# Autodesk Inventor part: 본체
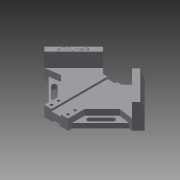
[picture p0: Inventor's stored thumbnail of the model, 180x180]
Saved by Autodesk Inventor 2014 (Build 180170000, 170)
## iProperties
Created: 2020-05
Part Number: 본체
Material: Generic
Document SubType Name: Modeling
Designer: kh
Density: 1 g/cm^3
Appearance: Default
Author: kh
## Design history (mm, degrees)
sketch "스케치1"
  geometry: L1 (0, 0)-(0, 178.142); L2 (0, 169.706)-(84.853, 84.853); L3 (84.853, 84.853)-(0, 0); L4 (0, 169.706)-(-84.853, 84.853); L5 (-84.853, 84.853)-(0, 0)
  constraints: 10 end point, 1 perpendicular, 1 point on line, 1 symmetric about line, 1 vertical
  dimensions: "d0" = 120 distance of L2.start L2.end; "d1" = 120 distance of L2.end L1.start
extrude "돌출1" new body sketch "스케치1" distance "d2" = 42; taper "d3" = 0 deg
sketch "스케치2"
  geometry: L1 (0, 0)-(84.853, 84.853) reference; L2 (84.853, 84.853)-(0, 169.706) reference; L3 (0, 169.706)-(-84.853, 84.853) reference; L4 (-84.853, 84.853)-(0, 0) reference; L5 (0, 169.706)-(-35.355, 134.35); L6 (-35.355, 134.35)-(0, 98.995); L7 (35.355, 134.35)-(0, 98.995); L8 (35.355, 134.35)-(0, 169.706); L9 (0, 169.706)-(0, 0); L10 (0, 0)-(0, 20); L11 (-20, 20)-(20, 20); L12 (0, 20)-(0, 115); L13 (-16.005, 115)-(16.005, 115); L14 (-20, 20)-(0, 0); L15 (0, 0)-(20, 20); 1 further point
  constraints: 22 end point, 8 point on line, 4 perpendicular, 2 collinear, 2 midpoint, 1 parallel, 1 vertical
  dimensions: "d4" = 50 distance of L5.end L6.end; "d5" = 50 distance of L7.start L6.end; "d6" = 20 distance of L1.start L10.end; "d7" = 95 distance of L10.end L12.end
  node "투영된 루프1"
extrude "돌출2" cut sketch "스케치2" stored distance "d8" = 42; taper "d9" = 0 deg
extrude "돌출3" cut sketch "스케치2" stored distance "d10" = 42; taper "d11" = 0 deg
sketch "스케치3"
  geometry: L1 (-20, 20)-(20, 20) reference; L2 (20, 20)-(84.853, 84.853) reference; L3 (84.853, 84.853)-(35.355, 134.35) reference; L4 (35.355, 134.35)-(16.005, 115) reference; L5 (16.005, 115)-(-16.005, 115) reference; L6 (-16.005, 115)-(-35.355, 134.35) reference; L7 (-35.355, 134.35)-(-84.853, 84.853) reference; L8 (-84.853, 84.853)-(-20, 20) reference; L9 (24.749, 123.744)-(74.246, 74.246); L10 (24.749, 123.744)-(35.355, 134.35); L11 (35.355, 134.35)-(84.853, 84.853); L12 (84.853, 84.853)-(74.246, 74.246); L13 (0, 0)-(0, 115); L14 (-84.853, 84.853)-(-35.355, 134.35); L15 (-24.749, 123.744)-(-74.246, 74.246); L16 (-24.749, 123.744)-(-35.355, 134.35); L17 (-35.355, 134.35)-(-84.853, 84.853); L18 (-84.853, 84.853)-(-74.246, 74.246); L19 (-24.749, 123.744)-(-16.005, 115); L20 (16.005, 115)-(24.749, 123.744); L21 (-16.005, 115)-(16.005, 115); L22 (-74.246, 74.246)-(-20, 20); L23 (-20, 20)-(20, 20); L24 (20, 20)-(74.246, 74.246)
  constraints: 32 end point, 8 collinear, 2 point on line, 2 symmetric about line, 1 midpoint, 1 parallel, 1 perpendicular
  dimensions: "d12" = 15 distance between parallel lines of L9 L3
extrude "돌출4" cut sketch "스케치3" distance "d13" = 24; taper "d14" = 0 deg
chamfer "모따기1" distance "d15" = 5; stored, may be unused: second distance "d16" = 15, angle "d17" = 45 deg
chamfer "모따기2" distance "d18" = 5; stored, may be unused: second distance "d19" = 15, angle "d20" = 45 deg
sketch "스케치4"
  geometry: L1 (20, 20)-(-20, 20) reference; L2 (74.246, 74.246)-(20, 20) reference; L3 (24.749, 123.744)-(74.246, 74.246) reference; L4 (16.005, 115)-(24.749, 123.744) reference; L5 (-16.005, 115)-(16.005, 115) reference; L6 (-24.749, 123.744)-(-16.005, 115) reference; L7 (-74.246, 74.246)-(-24.749, 123.744) reference; L8 (-20, 20)-(-74.246, 74.246) reference; L9 (0, 0)-(0, 115); L10 (-8, 115)-(8, 115); L11 (8, 115)-(8, 20); L12 (8, 20)-(-8, 20); L13 (-8, 20)-(-8, 115); L14 (20, 20)-(20, 48.284); L15 (20, 48.284)-(49.497, 77.782); L16 (49.497, 77.782)-(74.246, 74.246); L17 (84.853, 84.853)-(35.355, 134.35) reference; L18 (29.698, 46.669)-(49.497, 66.468); L19 (26.87, 49.497)-(46.669, 69.296); L20 (52.326, 63.64)-(32.527, 43.841); L21 (20, 27.071)-(68.059, 75.13); L22 (20, 20)-(74.246, 74.246); L23 (-49.497, 77.782)-(-74.246, 74.246); L24 (-24.749, 123.744)-(-74.246, 74.246); L25 (-20, 20)-(-74.246, 74.246); L26 (-26.87, 49.497)-(-46.669, 69.296); L27 (-20, 48.284)-(-49.497, 77.782); L28 (-29.698, 46.669)-(-49.497, 66.468); L29 (-52.326, 63.64)-(-32.527, 43.841); L30 (-20, 27.071)-(-68.059, 75.13); L31 (-74.246, 74.246)-(-20, 20); L32 (-20, 20)-(-20, 48.284); A1 r 4 centre (29.698, 46.669) between (26.87, 49.497) and (32.527, 43.841); A2 r 4 centre (49.497, 66.468) between (52.326, 63.64) and (46.669, 69.296); A3 r 4 centre (-49.497, 66.468) between (-46.669, 69.296) and (-52.326, 63.64); A4 r 4 centre (-29.698, 46.669) between (-32.527, 43.841) and (-26.87, 49.497); 3 further points
  constraints: 50 end point, 13 symmetric about line, 8 point on circle, 7 point on line, 5 parallel, 4 centre point, 4 tangent, 3 perpendicular, 2 midpoint, 1 horizontal, 3 other
  dimensions: "d21" = 16 distance of L10.start L10.end; "d27" = 20 distance from line of L9 L14.start; "d28" = 30 distance from line of L15.end L17; "d29" = 28 distance of L18.start L18.end; "d30" = 4 radius of A2; "d31" = 38 distance from line of L18.end L17; "d32" = 20 distance from line of L2 L15.end; "d33" = 12 distance from line of L2 L18.end; "d34" = 5 distance between parallel lines of L21 L2
  node "투영된 루프3"
extrude "돌출5" cut sketch "스케치4" distance "d22" = 3.5; taper "d23" = 0 deg
sketch "스케치5"
  geometry: L1 (-20, 20)-(20, 20) reference; L2 (84.853, 84.853)-(20, 20) reference; L3 (35.355, 134.35)-(84.853, 84.853) reference; L4 (35.355, 134.35)-(16.005, 115) reference; L5 (16.005, 115)-(-16.005, 115) reference; L6 (-16.005, 115)-(-35.355, 134.35) reference; L7 (-84.853, 84.853)-(-35.355, 134.35) reference; L8 (-20, 20)-(-84.853, 84.853) reference; L9 (0, 115)-(0, 0); L10 (-6, 115)-(6, 115); L11 (6, 115)-(6, 20); L12 (6, 20)-(-6, 20); L13 (-6, 20)-(-6, 115)
  constraints: 10 end point, 2 parallel, 2 perpendicular, 2 point on line, 1 horizontal, 1 midpoint, 1 other
  dimensions: "d24" = 12 distance of L10.start L10.end
extrude "돌출6" cut sketch "스케치5" distance "d25" = 3; taper "d26" = 0 deg
extrude "돌출7" cut sketch "스케치4" stored distance "d35" = 3; taper "d36" = 0 deg
extrude "돌출8" cut sketch "스케치4" distance "d37" = 10; taper "d38" = 0 deg
sketch "스케치6"
  geometry: L1 (20, 20)-(20, 48.284) reference; L2 (20, 48.284)-(49.497, 77.782) reference; L3 (49.497, 77.782)-(74.246, 74.246) reference; L4 (24.749, 123.744)-(74.246, 74.246) reference; L5 (16.005, 115)-(24.749, 123.744) reference; L6 (8, 115)-(16.005, 115) reference; L7 (8, 115)-(8, 20) reference; L8 (20, 20)-(8, 20) reference; 3 further points
  constraints: 1 vertical alignment
  dimensions: "d39" = 12 distance of point (14, 26) point (14, 38); "d40" = 6 distance from line of L8 point (14, 26); "d41" = 14 horizontal distance of point (0, 0) point (14, 26)
hole "구멍1" sketch "스케치6" at (14, 38), (14, 26) diameter "d42" = 4.5; stored, may be unused: countersink angle "d46" = 90 deg, drill point angle "d48" = 118 deg; dims "d43" = 6, "d44" = 4, "d45" = 2, "d47" = 8
sketch "스케치7"
  geometry: L1 (-74.246, 74.246)-(-68.059, 75.13) reference; L2 (-68.059, 75.13)-(-20, 27.071) reference; L3 (-20, 27.071)-(-20, 20) reference; L4 (-20, 20)-(-6, 20) reference; L5 (-6, 20)-(-6, 115) reference; L6 (-6, 115)-(-16.005, 115) reference; L7 (-16.005, 115)-(-35.355, 134.35) reference; L8 (-84.853, 84.853)-(-35.355, 134.35) reference; L9 (-74.246, 74.246)-(-84.853, 84.853) reference; L10 (-32.527, 43.841)-(-52.326, 63.64) reference; L11 (-46.669, 69.296)-(-26.87, 49.497) reference; C1 r 2.25 at (-14, 38) reference; C2 r 2.25 at (-14, 26) reference; C3 r 4 at (-14, 38); C4 r 4 at (-14, 26); A1 r 4 centre (-29.698, 46.669) between (-32.527, 43.841) and (-26.87, 49.497) reference; A2 r 4 centre (-49.497, 66.468) between (-46.669, 69.296) and (-52.326, 63.64) reference; 1 further point
  constraints: 2 centre point, 2 coincident
  dimensions: "d49" = 8 diameter of C3; "d50" = 8 diameter of C4
extrude "돌출9" cut sketch "스케치7" distance "d51" = 10; taper "d52" = 0 deg
sketch "스케치9"
  geometry: L1 (-37.257, 114.906)-(-65.888, 84.893); L2 (-65.888, 84.893)-(-70.233, 89.038); L3 (-70.233, 89.038)-(-41.602, 119.051); L4 (-41.602, 119.051)-(-37.257, 114.906); L5 (-37.257, 114.906)-(-70.233, 89.038); L6 (-81.317, 81.317)-(-31.82, 130.815) reference; L7 (-81.317, 81.317)-(-74.246, 74.246) reference; L8 (-74.246, 74.246)-(-24.749, 123.744) reference; L9 (-24.749, 123.744)-(-31.82, 130.815) reference; 2 further points
  constraints: 2 end point, 1 point on line, 2 other
  dimensions: "d53" = 5 distance from line of point (-53.033, 102.53) L8; "d54" = 35 distance from line of L9 point (-53.033, 102.53)
feature "엠보싱1" sketch "스케치9" dims "d4" = 50, "d5" = 50, "d6" = 20, "d7" = 95, "d55" = 0.5, "d56" = 0
node "솔리드1"
mirror "대칭1"
node "투영된 루프2"
node "투영된 루프4"
node "투영된 루프5"
node "투영된 루프6"
node "투영된 루프8"
